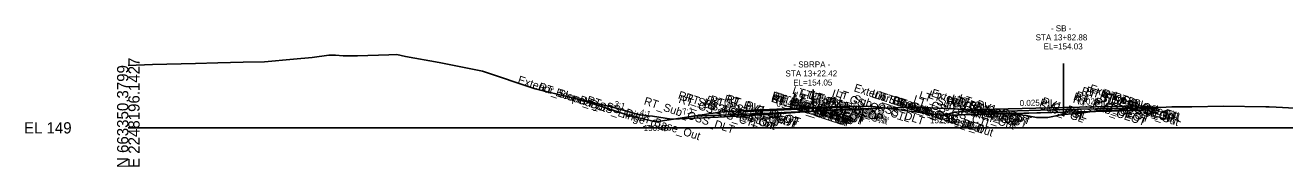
# Model space of a CAD drawing. Extents: x -26 to 2603, y -10 to 9566.
# Drawn here: x -25.7 to 288.1, y 6990.3 to 7025.5 of the extents above; entities that cross this region are included whole.
import ezdxf

# ---------------------------------------------------------------- set-up
doc = ezdxf.new("R2010")
doc.units = 0
for name, color, linetype in [('Default', 7, 'Continuous'), ('Exist Cross Section Cell', 7, 'Continuous'), ('Exist XS Ground Line', 7, 'Continuous'), ('Prop CMT Pvmt Course 1', 7, 'Continuous'), ('Prop CMT Pvmt Course 1 Wedge', 7, 'Continuous'), ('Prop CMT Pvmt Course 2', 7, 'Continuous'), ('Prop CMT Pvmt Course 2 Wedge', 7, 'Continuous'), ('Prop CMT Pvmt Course 3', 7, 'Continuous'), ('Prop CMT Pvmt Surface', 7, 'Continuous'), ('Prop CMT Pvmt Surface Overlay', 7, 'Continuous'), ('Prop CMT Pvmt Surface Shoulder', 7, 'Continuous'), ('Prop CMT Pvmt Wedge Surface 1', 7, 'Continuous'), ('Prop CMT Pvmt Wedge Surface 2', 7, 'Continuous'), ('Prop CMT Shld Paved Course 1', 7, 'Continuous'), ('Prop CMT Shld Paved Course 2', 7, 'Continuous'), ('Prop CMT Shld Paved Course 3', 7, 'Continuous'), ('Prop CMT Slope Grass', 7, 'Continuous'), ('Prop CMT Subgrade Earthwork', 7, 'Continuous'), ('Prop XS Ditch Standard Text', 7, 'Continuous'), ('Prop XS SE Text', 7, 'Continuous'), ('Prop XS Side Slope Text', 7, 'Continuous'), ('Prop XS Vertical Lines Alignments', 7, 'Continuous'), ('Scratch_Level_1', 7, 'Continuous'), ('Scratch_Level_9', 7, 'Continuous')]:
    doc.layers.add(name, color=color, linetype=linetype)

msp = doc.modelspace()

# ---------------------------------------------------------------- linework, layer by layer
at = {"layer": 'Exist Cross Section Cell'}
msp.add_line((0, 7000), (300, 7000), dxfattribs=at)
at = {"layer": 'Exist XS Ground Line'}
for p, q in [((41.12, 7017.09), (45.83, 7017.52)), ((45.83, 7017.52), (50, 7018.05)), ((50, 7018.05), (51.62, 7018.08)), ((51.62, 7018.08), (53.55, 7017.94)), ((53.55, 7017.94), (57.09, 7017.88)), ((57.09, 7017.88), (64.87, 7018.14)), ((64.87, 7018.14), (66.93, 7018.26)), ((66.93, 7018.26), (69.08, 7017.72)), ((69.08, 7017.72), (77.41, 7016.26)), ((0, 7015.53), (6.04, 7015.73)), ((6.04, 7015.73), (16.7, 7015.99)), ((16.7, 7015.99), (22.32, 7016.2)), ((22.32, 7016.2), (28.63, 7016.3)), ((28.63, 7016.3), (33.95, 7016.42)), ((33.95, 7016.42), (41.12, 7017.09)), ((77.41, 7016.26), (88.28, 7014.09)), ((88.28, 7014.09), (101.38, 7009.7)), ((101.38, 7009.7), (110.25, 7007.55)), ((110.25, 7007.55), (120.39, 7005.24)), ((120.39, 7005.24), (127.08, 7003.29)), ((179.54, 7004.65), (196.02, 7005.13)), ((196.02, 7005.13), (205.63, 7004.74)), ((249.04, 7004.77), (256.25, 7005.05)), ((256.25, 7005.05), (258.61, 7005.13)), ((258.61, 7005.13), (259.99, 7005.18)), ((259.99, 7005.18), (260.91, 7005.21)), ((260.91, 7005.21), (264.95, 7005.26)), ((264.95, 7005.26), (272.87, 7005.36)), ((272.87, 7005.36), (283.4, 7005.2)), ((283.4, 7005.2), (284.23, 7005.19)), ((284.23, 7005.19), (286.01, 7005.1)), ((286.01, 7005.1), (300, 7004.34)), ((127.08, 7003.29), (129.64, 7003.01)), ((129.64, 7003.01), (130.63, 7002.86)), ((130.63, 7002.86), (135.34, 7002.16)), ((135.34, 7002.16), (143.26, 7002.48)), ((143.26, 7002.48), (146.99, 7002.68)), ((146.99, 7002.68), (159.44, 7003.34)), ((159.44, 7003.34), (171.77, 7004.21)), ((171.77, 7004.21), (173.86, 7004.34)), ((173.86, 7004.34), (175.8, 7004.47)), ((175.8, 7004.47), (179.54, 7004.65)), ((205.63, 7004.74), (206.05, 7004.74)), ((206.05, 7004.74), (208.65, 7004.45)), ((208.65, 7004.45), (219.22, 7003.45)), ((219.22, 7003.45), (223.68, 7003.08)), ((223.68, 7003.08), (226.31, 7002.55)), ((226.31, 7002.55), (229.13, 7002.57)), ((229.13, 7002.57), (232.33, 7003.25)), ((232.33, 7003.25), (237.91, 7003.76)), ((237.91, 7003.76), (241.69, 7004.27)), ((241.69, 7004.27), (245.68, 7004.37)), ((245.68, 7004.37), (246.82, 7004.37)), ((246.82, 7004.37), (247.61, 7004.49)), ((247.61, 7004.49), (249.04, 7004.77))]:
    msp.add_line(p, q, dxfattribs=at)
at = {"layer": 'Prop CMT Pvmt Course 1'}
for points in [[(170.63, 7005.05), (157.97, 7004.51)], [(170.63, 7004.92), (179.14, 7005.28)], [(170.63, 7005.05), (174.9, 7005.23)], [(179.14, 7005.16), (170.63, 7004.8)], [(170.63, 7004.8), (170.63, 7005.05)], [(170.63, 7004.8), (170.63, 7005.05)], [(174.9, 7004.98), (170.63, 7004.8)], [(174.9, 7005.23), (174.9, 7004.98)], [(179.14, 7005.28), (179.14, 7005.16)], [(233, 7005.03), (215.84, 7004.6)], [(233, 7005.03), (245, 7005.33)], [(233, 7004.53), (233, 7005.03)], [(233, 7004.53), (233, 7005.03)], [(245, 7005.33), (245, 7004.83)], [(157.97, 7004.26), (170.63, 7004.8)], [(157.97, 7004.51), (157.97, 7004.26)], [(170.63, 7004.8), (170.63, 7004.92)], [(215.84, 7004.6), (215.84, 7004.1)], [(215.84, 7004.1), (233, 7004.53)], [(245, 7004.83), (233, 7004.53)]]:
    msp.add_lwpolyline(points, dxfattribs=at)
msp.add_lwpolyline([(170.63, 7004.8), (170.63, 7004.92), (170.63, 7004.92), (170.63, 7004.8)], close=True, dxfattribs=at)
at = {"layer": 'Prop CMT Pvmt Course 1 Wedge'}
for points in [[(179.14, 7005.28), (170.63, 7004.92)], [(170.63, 7004.92), (170.63, 7004.92)]]:
    msp.add_lwpolyline(points, dxfattribs=at)
at = {"layer": 'Prop CMT Pvmt Course 2'}
for points in [[(170.63, 7004.8), (174.9, 7004.98)], [(174.9, 7004.98), (174.9, 7004.31)], [(170.63, 7004.8), (157.97, 7004.26)], [(157.97, 7004.26), (157.97, 7003.6)], [(157.97, 7003.6), (170.63, 7004.13)], [(170.63, 7004.13), (170.63, 7004.8)], [(170.63, 7004.13), (170.63, 7004.8)], [(174.9, 7004.31), (170.63, 7004.13)], [(233, 7004.53), (215.84, 7004.1)], [(215.84, 7004.1), (215.84, 7003.43)], [(215.84, 7003.43), (233, 7003.86)], [(233, 7004.53), (245, 7004.83)], [(233, 7003.86), (233, 7004.53)], [(233, 7003.86), (233, 7004.53)], [(245, 7004.16), (233, 7003.86)], [(245, 7004.83), (245, 7004.16)]]:
    msp.add_lwpolyline(points, dxfattribs=at)
at = {"layer": 'Prop CMT Pvmt Course 2 Wedge'}
for points in [[(179.14, 7005.16), (170.63, 7004.8)], [(170.63, 7004.8), (170.63, 7004.8)]]:
    msp.add_lwpolyline(points, dxfattribs=at)
at = {"layer": 'Prop CMT Pvmt Course 3'}
for points in [[(170.63, 7004.13), (157.97, 7003.6)], [(157.97, 7003.59), (170.63, 7004.12)], [(157.97, 7003.6), (157.97, 7003.59)], [(170.63, 7004.13), (174.9, 7004.31)], [(174.9, 7004.3), (170.63, 7004.12)], [(170.63, 7004.12), (170.63, 7004.13)], [(170.63, 7004.12), (170.63, 7004.13)], [(174.9, 7004.31), (174.9, 7004.3)]]:
    msp.add_lwpolyline(points, dxfattribs=at)
at = {"layer": 'Prop CMT Pvmt Surface'}
for points in [[(170.63, 7005.05), (157.97, 7004.51)], [(170.63, 7005.05), (174.9, 7005.23)], [(233, 7005.03), (215.84, 7004.6)], [(233, 7005.03), (245, 7005.33)]]:
    msp.add_lwpolyline(points, dxfattribs=at)
at = {"layer": 'Prop CMT Pvmt Surface Overlay'}
for points in [[(233, 7005.03), (215.84, 7004.6)], [(233, 7005.03), (245, 7005.33)]]:
    msp.add_lwpolyline(points, dxfattribs=at)
at = {"layer": 'Prop CMT Pvmt Surface Shoulder'}
for points in [[(174.9, 7005.23), (179.14, 7005.41)], [(245, 7005.33), (251, 7005.48)], [(157.97, 7004.51), (153.75, 7004.34)], [(215.84, 7004.6), (213.84, 7004.55)]]:
    msp.add_lwpolyline(points, dxfattribs=at)
at = {"layer": 'Prop CMT Pvmt Wedge Surface 1'}
for points in [[(179.14, 7005.28), (170.63, 7004.92)], [(170.63, 7004.8), (179.14, 7005.16)], [(170.63, 7005.05), (170.63, 7004.8)], [(170.63, 7005.05), (170.63, 7004.8), (170.63, 7004.8), (170.63, 7004.92), (170.63, 7004.92), (170.63, 7004.8)], [(170.63, 7004.8), (174.9, 7004.98)], [(174.9, 7004.98), (174.9, 7005.23)], [(179.14, 7005.16), (179.14, 7005.28)], [(170.63, 7004.8), (157.97, 7004.26)], [(157.97, 7004.26), (157.97, 7004.51)], [(170.63, 7004.92), (170.63, 7004.8)]]:
    msp.add_lwpolyline(points, dxfattribs=at)
at = {"layer": 'Prop CMT Pvmt Wedge Surface 2'}
for points in [[(170.63, 7005.05), (170.63, 7004.8)], [(170.63, 7005.05), (170.63, 7004.8)], [(170.63, 7004.8), (174.9, 7004.98)], [(174.9, 7004.98), (174.9, 7005.23)], [(170.63, 7004.8), (157.97, 7004.26)], [(157.97, 7004.26), (157.97, 7004.51)]]:
    msp.add_lwpolyline(points, dxfattribs=at)
at = {"layer": 'Prop CMT Shld Paved Course 1'}
for points in [[(174.9, 7005.23), (179.14, 7005.41), (179.4, 7005.17)], [(174.9, 7004.98), (174.9, 7005.23)], [(179.4, 7005.17), (174.9, 7004.98)], [(245, 7005.33), (251, 7005.48), (251.49, 7004.99)], [(245, 7004.83), (245, 7005.33)], [(251.49, 7004.99), (245, 7004.83)], [(157.97, 7004.51), (153.75, 7004.34), (153.47, 7004.07)], [(153.47, 7004.07), (157.97, 7004.26)], [(157.97, 7004.26), (157.97, 7004.51)], [(215.84, 7004.6), (213.84, 7004.55), (213.32, 7004.04)], [(213.32, 7004.04), (215.84, 7004.1)], [(215.84, 7004.1), (215.84, 7004.6)]]:
    msp.add_lwpolyline(points, dxfattribs=at)
at = {"layer": 'Prop CMT Shld Paved Course 2'}
for points in [[(174.9, 7004.98), (179.4, 7005.17), (180.08, 7004.53)], [(174.9, 7004.31), (174.9, 7004.98)], [(245, 7004.83), (251.49, 7004.99), (251.99, 7005), (252.64, 7004.35)], [(157.97, 7004.26), (153.47, 7004.07), (152.73, 7003.38)], [(152.73, 7003.38), (157.97, 7003.6)], [(157.97, 7003.6), (157.97, 7004.26)], [(180.08, 7004.53), (174.9, 7004.31)], [(215.84, 7004.1), (213.32, 7004.04), (212.82, 7004.02), (212.14, 7003.34)], [(212.14, 7003.34), (215.84, 7003.43)], [(215.84, 7003.43), (215.84, 7004.1)], [(245, 7004.16), (245, 7004.83)], [(252.64, 7004.35), (245, 7004.16)]]:
    msp.add_lwpolyline(points, dxfattribs=at)
at = {"layer": 'Prop CMT Shld Paved Course 3'}
for points in [[(157.97, 7003.6), (152.73, 7003.38), (152.21, 7003.35), (152.2, 7003.34)], [(152.2, 7003.34), (157.97, 7003.59)], [(157.97, 7003.59), (157.97, 7003.6)], [(174.9, 7004.31), (180.08, 7004.53), (180.61, 7004.55), (180.62, 7004.54)], [(180.62, 7004.54), (174.9, 7004.3)], [(174.9, 7004.3), (174.9, 7004.31)]]:
    msp.add_lwpolyline(points, dxfattribs=at)
at = {"layer": 'Prop CMT Slope Grass'}
for points in [[(131.42, 7001.46), (125.07, 7003), (112.24, 7007.11)], [(179.14, 7005.41), (185.54, 7005.32), (203.2, 7003.03)], [(251, 7005.48), (253, 7005.41)], [(253, 7005.41), (254.68, 7004.99)], [(153.75, 7004.34), (147.42, 7003.89), (131.42, 7001.46)], [(205.84, 7003.91), (203.2, 7003.03)], [(213.84, 7004.55), (205.84, 7003.91)]]:
    msp.add_lwpolyline(points, dxfattribs=at)
at = {"layer": 'Prop CMT Subgrade Earthwork'}
msp.add_line((252.64, 7004.35), (254.68, 7004.99), dxfattribs=at)
for points in [[(152.2, 7003.34), (140.65, 7002.86)], [(157.97, 7003.59), (152.2, 7003.34)], [(170.63, 7004.12), (157.97, 7003.59)], [(170.63, 7004.12), (174.9, 7004.3)], [(174.9, 7004.3), (180.62, 7004.54)], [(180.62, 7004.54), (187.05, 7004.82)], [(252.64, 7004.35), (203.48, 7003.12)], [(212.14, 7003.34), (203.48, 7003.12)], [(215.84, 7003.43), (212.14, 7003.34)], [(233, 7003.86), (215.84, 7003.43)], [(233, 7003.86), (245, 7004.16)], [(245, 7004.16), (252.64, 7004.35)]]:
    msp.add_lwpolyline(points, dxfattribs=at)
at = {"layer": 'Prop XS Vertical Lines Alignments'}
for p, q in [((233, 7016.03), (233, 7003.03)), ((170.64, 7009.53), (170.64, 7005.05))]:
    msp.add_line(p, q, dxfattribs=at)

# ---------------------------------------------------------------- texts
at = {"layer": 'Default'}
msp.add_text('-', height=0.0001, dxfattribs=at).set_placement((0, 7000))
at = {"layer": 'Exist Cross Section Cell'}
for s, p in [('N 663350.3799', (0, 6990)), ('E 2248196.1427', (2.8, 6990))]:
    msp.add_text(s, height=2.8, rotation=90, dxfattribs=at).set_placement(p)
msp.add_text('EL 149', height=2.8, dxfattribs=at).set_placement((-26, 6998.6))
at = {"layer": 'Prop XS Ditch Standard Text'}
for s, p in [('152.03', (199.74, 7001.14)), ('150.46', (128.4, 6999.21))]:
    msp.add_text(s, height=1.5, dxfattribs=at).set_placement(p)
at = {"layer": 'Prop XS SE Text'}
for s, rotation, p in [('0.042', 2.4155, (161.51, 7005.18)), ('0.042', 2.4155, (171.45, 7005.78)), ('0.025', 1.4518, (222.1, 7005.39)), ('0.025', 1.4518, (236.94, 7005.77))]:
    msp.add_text(s, height=1.5, rotation=rotation, dxfattribs=at).set_placement(p)
at = {"layer": 'Prop XS Side Slope Text'}
for s, rotation, p in [('3:1', 343.5862, (120.9, 7005.34)), ('7:1', 8.6256, (138.13, 7003.24)), ('VAR.', 352.6047, (191.99, 7005.16)), ('3:1', 18.4349, (203.68, 7004.09)), ('4:1', 346.3907, (127.27, 7003.24))]:
    msp.add_text(s, height=1.5, rotation=rotation, dxfattribs=at).set_placement(p)
at = {"layer": 'Prop XS Vertical Lines Alignments'}
for s, p in [('- SB -', (229.86, 7024)), ('STA 13+82.88', (226.06, 7021.75)), ('- SBRPA -', (165.69, 7015.02)), ('STA 13+22.42', (163.74, 7012.77))]:
    msp.add_text(s, height=1.5, dxfattribs=at).set_placement(p)
at = {"layer": 'Scratch_Level_1'}
for s, p in [('EL=154.03', (228.03, 7019.5)), ('EL=154.05', (165.66, 7010.52))]:
    msp.add_text(s, height=1.5, dxfattribs=at).set_placement(p)
at = {"layer": 'Scratch_Level_9'}
for s, p in [('Exterior Boundary', (96.86, 7011.12)), ('RT_Slope_Cut', (102.04, 7009.42)), ('RT_Sub_Trench_Out', (136.83, 7007.34)), ('RT_GS_OS_CTL', (136.97, 7006.28)), ('RT_PS3_Shelf_Out', (138.54, 7006.8)), ('RT_PS1_OEOP', (144.66, 7006.27)), ('RT_PV2_OEOT', (148.28, 7006.4)), ('RT_PV1_OEOT', (148.82, 7006.47)), ('RT_Sub_OEEOP', (160.02, 7006.56)), ('LT_Sub_OEEOP', (160.07, 7006.54)), ('RT_PV2_OEEOP', (160.11, 7007.2)), ('RT_PV3_OEEOP', (160.11, 7006.54)), ('LT_PV2_OEEOP', (160.16, 7007.19)), ('LT_PV3_OEEOP', (160.16, 7006.52)), ('RT_PV1_OEEOP', (160.65, 7007.15)), ('LT_PV1_OEEOP', (160.7, 7007.14)), ('RT_PV2_IEEOP', (160.73, 7007)), ('RT_PV1_IEEOP', (161.26, 7006.95)), ('LT_Sub_OEOT', (165.16, 7006.45)), ('LT_PV2_OEOT', (165.25, 7007.1)), ('LT_PV3_OEOT', (165.25, 7006.43)), ('LT_Sub_Trench_Out', (165.3, 7008.53)), ('LT_PV1_OEOT', (165.79, 7007.17)), ('LT_PS3_Shelf_Out', (166.98, 7007.98)), ('LT_PV2_IEEOP', (169.29, 7007.35)), ('LT_PS2_OEOP', (169.81, 7007.27)), ('LT_PV1_IEEOP', (169.82, 7007.3)), ('LT_PS1_OEOP', (170.09, 7007.33)), ('LT_PS3_OEOP', (170.49, 7006.63)), ('LT_GS_OS_CTL', (175.13, 7007.69)), ('LT_Sub_OSS_DLT', (176.06, 7007.86)), ('Exterior Boundary', (180.64, 7009.13)), ('LT_SS_Ditch_Base_Out', (184.98, 7007.68)), ('LT_Slope_Cut', (185.86, 7007.41)), ('LT_SS_Ditch_Base_Out', (187.43, 7006.9)), ('LT_GS_OS_CTL', (195.43, 7006.28)), ('LT_Sub_Trench_Out', (196.82, 7007.33)), ('LT_PS2_Shelf_Out', (199.2, 7007.46)), ('Exterior Boundary', (199.91, 7007.86)), ('LT_PS1_OEOP', (204.79, 7006.47)), ('LT_PV1_OEOT', (206.73, 7006.54)), ('RT_Sub_OEOT', (235.22, 7006.33)), ('RT_PV2_OEOT', (235.31, 7006.97)), ('RT_PV1_OEOT', (235.85, 7007.29)), ('RT_Sub_Trench_Out', (237.28, 7008.36)), ('RT_PS2_Shelf_Out', (238.32, 7008.45)), ('Exterior Boundary', (239.3, 7009)), ('RT_PS2_OEOP', (241.86, 7007.11)), ('RT_PS1_OEOP', (241.91, 7007.42)), ('RT_GS_OS_CTL', (242.55, 7007.8)), ('RT_Slope_Fill', (245.32, 7007.02)), ('RT_SS_Hinge_Cut', (112.21, 7006.18)), ('RT_SS_Ditch_Base_Out', (114.04, 7006.13)), ('RT_Sub_OSS_DLT', (128.32, 7005.86)), ('RT_PS3_OEOP', (143.1, 7005.49)), ('RT_PS2_OEOP', (143.84, 7006.19)), ('RT_Sub_OEOT', (148.19, 7005.75)), ('RT_PV3_OEOT', (148.28, 7005.73)), ('PV2_PGL', (164.53, 7005.75)), ('PV1_PGL', (165.06, 7005.82)), ('RT_Sub_OSS_DLT', (190.28, 7006.11)), ('LT_Sub_OSS_DLT', (190.33, 7006.09)), ('LT_PS2_OEOP', (203.74, 7006.14)), ('LT_Slope_Cut', (205.13, 7006.14)), ('LT_Sub_OEOT', (206.11, 7005.58)), ('LT_PV2_OEOT', (206.2, 7006.22)), ('Sub_PGL', (226.81, 7004.85)), ('PV2_PGL', (226.9, 7005.48)), ('PV1_PGL', (227.44, 7005.81))]:
    msp.add_text(s, height=2, rotation=341.787, dxfattribs=at).set_placement(p)

doc.saveas('drawing.dxf')
